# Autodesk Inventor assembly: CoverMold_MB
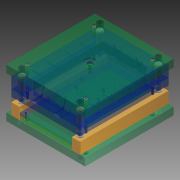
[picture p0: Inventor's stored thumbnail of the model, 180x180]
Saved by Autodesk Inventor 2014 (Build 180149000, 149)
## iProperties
Created: 2009-12
Part Number: CoverMold_MB
Document SubType Name: Assembly
Designer: gaom
Author: gaom
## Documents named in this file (20)
- C:\Users\iTools\Desktop\tutorial files\Mold\CoverMold\Cover Mold\MB\HASCO_No1 1\CoverMold_MB.iam
- C:\Users\iTools\Desktop\tutorial files\Mold\CoverMold\Libraries\Content Center Files\en-US\Z31\Z31-M12x45.ipt
- C:\Users\iTools\Desktop\tutorial files\Mold\CoverMold\Libraries\Content Center Files\en-US\Z10\Z10 -66-42.ipt
- C:\Users\iTools\Desktop\tutorial files\Mold\CoverMold\Libraries\Content Center Files\en-US\Z20\Z20-54x200.ipt
- C:\Users\iTools\Desktop\tutorial files\Mold\CoverMold\Libraries\Content Center Files\en-US\Z31\Z31-M20x80.ipt
- C:\Users\iTools\Desktop\tutorial files\Mold\CoverMold\Cover Mold\MB\HASCO_No1 1\CoverMold_MB_K30.ipt
- C:\Users\iTools\Desktop\tutorial files\Mold\CoverMold\Cover Mold\MB\HASCO_No1 1\CoverMold_MB_K401.ipt
- C:\Users\iTools\Desktop\tutorial files\Mold\CoverMold\Cover Mold\MB\HASCO_No1 1\CoverMold_MB_K402.ipt
- C:\Users\iTools\Desktop\tutorial files\Mold\CoverMold\Cover Mold\MB\HASCO_No1 1\CoverMold_MB_K60.ipt
- C:\Users\iTools\Desktop\tutorial files\Mold\CoverMold\Libraries\Content Center Files\en-US\Z00\Z00-42-116x95.ipt
- C:\Users\iTools\Desktop\tutorial files\Mold\CoverMold\Cover Mold\MB\HASCO_No1 1\CoverMold_MB_K70.ipt
- C:\Users\iTools\Desktop\tutorial files\Mold\CoverMold\Libraries\Content Center Files\en-US\Z1052-3\Z1052-3-20x5.ipt
- C:\Users\iTools\Desktop\tutorial files\Mold\CoverMold\Cover Mold\MB\HASCO_No1 1\CoverMold_MB_K20.ipt
- C:\Users\iTools\Desktop\tutorial files\Mold\CoverMold\Cover Mold\MB\HASCO_No1 1\CoverMold_MB_K11.ipt
- C:\Users\iTools\Desktop\tutorial files\Mold\CoverMold\Libraries\Content Center Files\en-US\Z10\Z10 -66-40.ipt
- C:\Users\iTools\Desktop\tutorial files\Mold\CoverMold\Libraries\Content Center Files\en-US\Z31\Z31-M20x240.ipt
- C:\Users\iTools\Desktop\tutorial files\Mold\CoverMold\Cover Mold\MB\HASCO_No1 1\CoverMold_MB_K11_1.ipt
- C:\Users\iTools\Desktop\tutorial files\Mold\CoverMold\Libraries\Content Center Files\en-US\Z00\Z00-40-116x95.ipt
- C:\Users\iTools\Desktop\tutorial files\Mold\CoverMold\Cover Mold\MB\HASCO_No1 1\CoverMold_MB_K20_1.ipt
- C:\Users\iTools\Desktop\tutorial files\Mold\CoverMold\Libraries\Content Center Files\en-US\Z33\Z33-4x10.ipt
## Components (41 placed, 19 different names)
1. Z10 66/42:1 — Insert:2
2. CoverMold_MB_K30:1 — Flush:2, Flush:3, Mate:2, Mate:3, Mate:4
3. CoverMold_MB_K401:1 — Flush:4, Flush:6, Mate:3, Mate:11
4. CoverMold_MB_K402:2 — Flush:5, Flush:7, Mate:4, Mate:12
5. CoverMold_MB_K60:1 — Flush:8, Flush:9, Mate:5
6. Z00 42-116x95:1 — Insert:4
7. CoverMold_MB_K70:1 — Insert:1, Mate:5, Flush:10, Flush:11, Ejection, Mate:7, Mate:8
8. Z00 42-116x95:2 — Insert:5
9. Z10 66/42:2 — Insert:6
10. CoverMold_MB_K20:1 — Insert:4, Insert:5, Insert:7, Insert:11, Flush:12, Flush:13, Mate:9, PL1, Flush:18
11. CoverMold_MB_K11:1 — Insert:3, Mate:9, Flush:14, Flush:15
12. Z00 42-116x95:3 — Insert:7
13. Z10 66/40:1 — Insert:8
14. CoverMold_MB_K11_1:2 — Insert:9, Flush:1, Mate:1, Ejection, Flush:16, Mate:10, Mate:11, Mate:12
15. Z10 66/42:3 — Insert:10
16. Z00 40-116x95:1 — Insert:11
17. CoverMold_MB_K20_1:1 — Insert:2, Insert:6, Insert:8, Insert:10, Mate:2, Flush:17, Mate:13, PL1
18. Z33 4x10:1 — Mate:15
19. Z33 4x10:2
20. Z33 4x10:3
21. Z33 4x10:4
22. Z31 M20x240:1 — Insert:9
23. Z31 M20x240:2
24. Z31 M20x240:3
25. Z31 M20x240:4
26. Z1052-3 3/20x5:1 — Mate:7, Mate:8, Mate:15
27. Z1052-3 3/20x5:2
28. Z1052-3 3/20x5:3
29. Z1052-3 3/20x5:4
30. Z20 54x200:1 — Flush:1, Mate:1
31. Z20 54x200:2
32. Z20 54x200:3
33. Z20 54x200:4
34. Z31 M12x45:1 — Insert:1
35. Z31 M12x45:2
36. Z31 M12x45:3
37. Z31 M12x45:4
38. Z31 M20x80:1 — Insert:3
39. Z31 M20x80:2
40. Z31 M20x80:3
41. Z31 M20x80:4
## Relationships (44: Flush 18, Mate 15, Insert 11)
- Insert:1: CoverMold_MB_K70:1 ↔ Z31 M12x45:1
- Insert:2: Z10 66/42:1 ↔ CoverMold_MB_K20_1:1
- Insert:3: CoverMold_MB_K11:1 ↔ Z31 M20x80:1
- Insert:4: Z00 42-116x95:1 ↔ CoverMold_MB_K20:1
- Insert:5: Z00 42-116x95:2 ↔ CoverMold_MB_K20:1
- Insert:6: Z10 66/42:2 ↔ CoverMold_MB_K20_1:1
- Insert:7: CoverMold_MB_K20:1 ↔ Z00 42-116x95:3
- Insert:8: Z10 66/40:1 ↔ CoverMold_MB_K20_1:1
- Insert:9: CoverMold_MB_K11_1:2 ↔ Z31 M20x240:1
- Insert:10: Z10 66/42:3 ↔ CoverMold_MB_K20_1:1
- Insert:11: CoverMold_MB_K20:1 ↔ Z00 40-116x95:1
- Flush:1: CoverMold_MB_K11_1:2 ↔ Z20 54x200:1
- Mate:1: CoverMold_MB_K11_1:2 ↔ Z20 54x200:1
- Flush:2: CoverMold_MB_K30:1
- Flush:3: CoverMold_MB_K30:1
- Mate:2: CoverMold_MB_K30:1 ↔ CoverMold_MB_K20_1:1
- Flush:4: CoverMold_MB_K401:1
- Flush:5: CoverMold_MB_K402:2
- Flush:6: CoverMold_MB_K401:1
- Flush:7: CoverMold_MB_K402:2
- Mate:3: CoverMold_MB_K30:1 ↔ CoverMold_MB_K401:1
- Mate:4: CoverMold_MB_K30:1 ↔ CoverMold_MB_K402:2
- Flush:8: CoverMold_MB_K60:1
- Flush:9: CoverMold_MB_K60:1
- Mate:5: CoverMold_MB_K60:1 ↔ CoverMold_MB_K70:1
- Flush:10: CoverMold_MB_K70:1
- Flush:11: CoverMold_MB_K70:1
- Ejection [Mate]: CoverMold_MB_K70:1 ↔ CoverMold_MB_K11_1:2
- Mate:7: CoverMold_MB_K70:1 ↔ Z1052-3 3/20x5:1
- Mate:8: CoverMold_MB_K70:1 ↔ Z1052-3 3/20x5:1
- Flush:12: CoverMold_MB_K20:1
- Flush:13: CoverMold_MB_K20:1
- Mate:9: CoverMold_MB_K20:1 ↔ CoverMold_MB_K11:1
- Flush:14: CoverMold_MB_K11:1
- Flush:15: CoverMold_MB_K11:1
- Flush:16: CoverMold_MB_K11_1:2
- Mate:10: CoverMold_MB_K11_1:2
- Mate:11: CoverMold_MB_K401:1 ↔ CoverMold_MB_K11_1:2
- Mate:12: CoverMold_MB_K402:2 ↔ CoverMold_MB_K11_1:2
- Flush:17: CoverMold_MB_K20_1:1
- Mate:13: CoverMold_MB_K20_1:1
- PL1 [Mate]: CoverMold_MB_K20:1 ↔ CoverMold_MB_K20_1:1
- Mate:15: Z33 4x10:1 ↔ Z1052-3 3/20x5:1
- Flush:18: CoverMold_MB_K20:1
